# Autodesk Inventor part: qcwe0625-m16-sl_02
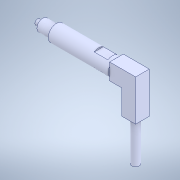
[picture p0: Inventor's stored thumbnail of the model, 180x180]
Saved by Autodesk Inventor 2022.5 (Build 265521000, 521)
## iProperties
Created: 2023-04
Part Number: qcwe0625-m16-sl_02
Material: Generic
Document SubType Name: Modeling
Designer: ImaoCorp
Density: 1 g/cm^3
Appearance: Default
Author: ImaoCorp
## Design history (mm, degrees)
feature "qcwe0625-m16-sl_02"
node "ソリッド1"
